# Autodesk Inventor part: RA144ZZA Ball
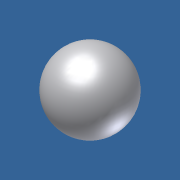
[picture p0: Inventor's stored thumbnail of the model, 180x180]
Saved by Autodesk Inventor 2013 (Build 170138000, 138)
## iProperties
Category: PARTsolutions
Created: 2011-07
Part Number: RA144ZZA Ball
Catalog Web Link: www.cadenas.de
Description: Six types b - Inch system sizes
Document SubType Name: Modeling
Designer: PARTsolutions
Density: 1 g/cm^3
Material: Générique
NB: RA144ZZA Ball
NN: Six types b
NT: Inch system sizes
NBSYN: RA144ZZA Ball
LINA: RA144ZZA Ball
SD: 3.175
D: 6.350
B: 2.380
B1: 2.779
D1: 7.52
D2: 7.52
C1: 0.58
C2: 0.79
R: 0.08
ORDER: RA144ZZA
CR: 284
COR: 96
CRF: 29
CORF: 10
LSG: 59000
LSO: 70000
MASS: 0.27
ORDER1: R144
WSS: RA144ZA
WDS: RA144ZZA
UTWF: FLR144
FORSS: FLRA144ZA
FORDS: FLRA144ZZA
DA1: 3.9
DA2: 4
DA: 5.5
RAS: 0.08
MASS1: 0.33
VERS: 3
X: 1.587
N: 9
O: 14.954
RB: 0.470
KT: DUMMY
SUPPLIER: NTN
ARTICLENO: RA144ZZA Ball
BOMINFO: RA144ZZA Ball
CREATOR: CADENAS GmbH
PSOL_IDENT_0: {\\10.0.0.251\ps_data\23d-libs\ntn\ball_roller_bearings\miniature_extra_small_bb\inch_system_sizes\i
PSOL_IDENT_1: ss_ball.prj},176 {VTYP=3D},{NB=RA144ZZA Ball},{LINA=RA144ZZA Ball},{NN=Six types b},{DATE=11.12.2007
PSOL_IDENT_2: 08:48:22},{GEOMDATE=08.02.2007 08:30:00},{VERSION=},{LINEID=16080},{LINESUBID=-1},{WBVAR=}  {NB=RA1
PSOL_IDENT_3: 44ZZA Ball},{LINA=RA144ZZA Ball},{KT=DUMMY},{IDNR=},{SD=3.175},{D=6.350},{B=2.380},{B1=2.779},{D1=7.
PSOL_IDENT_4: 52},{D2=7.52},{C1=0.58},{C2=0.79},{R=0.08},{ORDER=RA144ZZA},{CR=284},{COR=96},{CRF=29},{CORF=10},{LS
PSOL_IDENT_5: G=59000},{LSO=70000},{MASS=0.27},{ORDER1=R144},{WSS=RA144ZA},{WDS=RA144ZZA},{UTWF=FLR144},{FORSS=FLR
PSOL_IDENT_6: A144ZA},{FORDS=FLRA144ZZA},{DA1=3.9},{DA2=4},{DA=5.5},{RAS=0.08},{MASS1=0.33},{VERS=3},{X=1.5875},{N
PSOL_IDENT_7: =9},{O=14.95425},{RB=0.4699}
Title: RA144ZZA Ball
Author: Cadenas PARTsolutions
Comments: Inch system sizes
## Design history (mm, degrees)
sketch "Sketch_1"
  geometry: L1 (0.47, 0)-(-0.47, 0); L2 (0.47, 0)-(-0.47, 0); A1 r 0.47 centre (0, 0) between (0.47, 0) and (-0.47, 0)
  constraints: 4 end point, 2 point on circle, 1 centre point
revolve "Revolution1" sketch "Sketch_1" stored, may be unused: angle "d0" = 360 deg
node "iss_ball_XY"
node "iss_ball_YZ"
node "iss_ball_ZX"
node "iss_ball_X"
node "iss_ball_Y"
node "iss_ball_Z"
node "iss_ball_Center"
node "Solide1"
node "Corps solides"
node "Corps surfaciques"
